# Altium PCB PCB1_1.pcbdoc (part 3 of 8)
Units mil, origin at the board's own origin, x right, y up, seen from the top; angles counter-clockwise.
Board outline 3937.01 x 3346.46 mil, 6 copper layers (Top Layer, Signal-1, SIG, POWER, Signal-4, Bottom Layer), stack 60.565 mil thick; 256 components, 201 nets, 1360 pads, 815 vias.
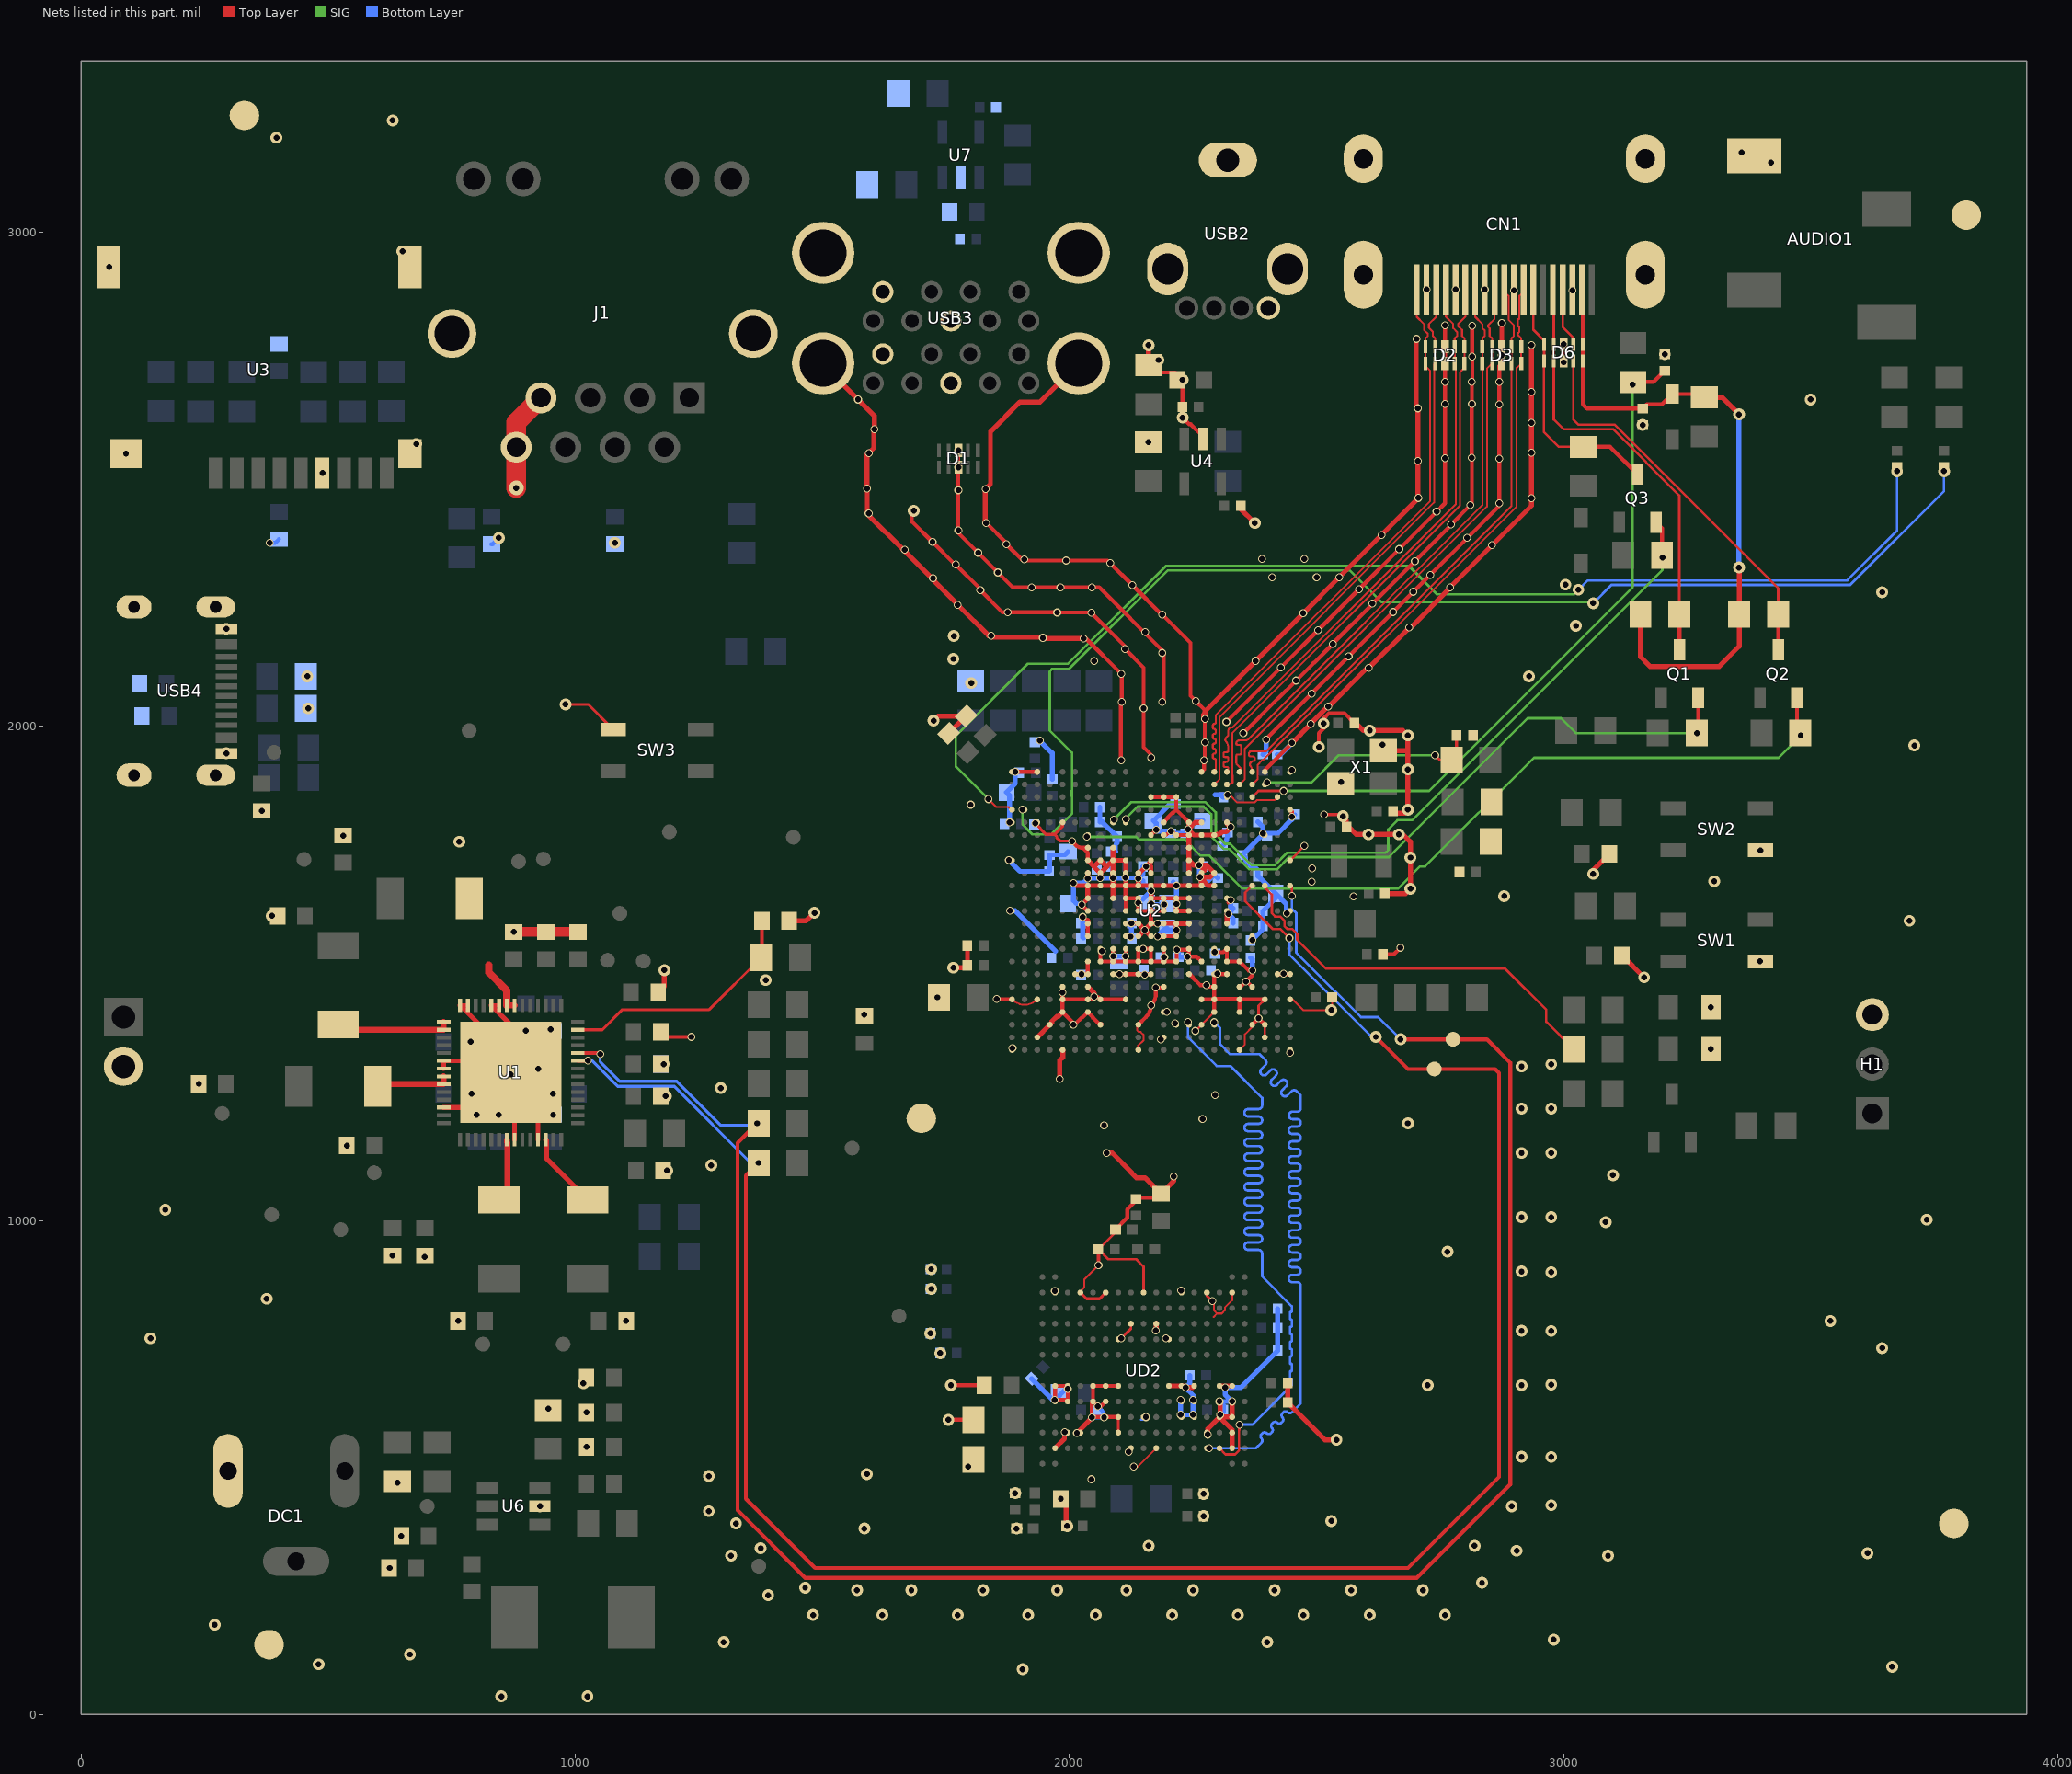
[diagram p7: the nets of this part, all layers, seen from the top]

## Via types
v1: diameter 16, hole 12, Top Layer to Bottom Layer, 426 vias
v2: diameter 24, hole 12, Top Layer to Bottom Layer, 385 vias
v3: diameter 34, hole 12, Top Layer to Bottom Layer, 2 vias
v4: diameter 30, hole 12, Top Layer to Bottom Layer, 2 vias

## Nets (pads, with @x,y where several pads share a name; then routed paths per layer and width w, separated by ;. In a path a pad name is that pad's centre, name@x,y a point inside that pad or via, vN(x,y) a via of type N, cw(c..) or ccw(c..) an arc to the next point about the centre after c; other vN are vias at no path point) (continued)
GND: AUDIO1.1 C1.1 C2.1 C3.1 C4.1 C5.1 C6.1 C7.1 C8.1 C9.1 C10.1 C11.1 C12.1 C13.1 C14.1 C15.1 C16.1 C17.1 C18.1 C19.1 C20.1 C21.1 C24.1 C25.2 C26.1 C27.1 C28.1 C29.1 C30.1 C31.1 C32.1 C33.1 C34.1 C35.1 C36.1 C37.1 C38.1 C39.1 C40.1 C41.1 C42.1 C43.1 C44.1 C45.1 C46.1 C47.1 C48.1 C49.1 C50.1 C51.1 C52.1 C53.1 C54.1 C55.1 C56.1 C57.1 C58.1 C59.1 C60.1 C61.1 C62.1 C63.1 C64.1 C65.1 C66.1 C67.1 C68.1 C69.1 C70.1 C71.1 C72.1 C73.1 C74.1 C75.1 C76.1 C77.1 C78.1 C79.1 C80.1 C81.1 C82.1 C83.1 C84.1 C85.1 C86.2 C87.2 C88.2 C89.2 C90.1 C91.1 C92.1 C93.1 C94.1 C95.1 C96.1 C97.1 C98.1 C99.1 C100.1 C101.1 C102.1 C103.1 C104.1 C105.1 C106.1 C107.1 C108.1 C109.1 C110.1 C111.1 C112.1 C113.1 C114.1 C115.1 C116.1 C117.1 C118.1 C119.1 C120.1 C121.1 C122.1 C123.2 C124.1 C125.2 C126.1 C127.1 C128.2 C129.1 C130.1 C131.1 C132.2 C135.1 C136.1 C137.1 C138.1 C139.2 C140.2 C141.1 C142.2 C143.2 C144.2 C147.1 C148.1 C149.2 CN1.2 CN1.5 CN1.8 CN1.11 CN1.17 CN1.20 CN1.21 CN1.22 CN1.23 D1.3 D1.8 D2.3 D2.8 D3.3 D3.8 D6.3 D6.8 DC1.2 H1.3 H2.2 J1.7 J1.8 J1.SH1 J1.SH2 LED1.1 LED2.1 pad.1@330,3236.46 pad.1@3815,3034.92 pad.2@3790,386.46 pad.3@380,141.46 pad.4@1700,1206.46 R7.2 R16.1 R17.1 R18.2 R21.1 R24.1 R30.2 R31.1 R34.1 R37.1 R38.1 R44.1 R55.1 R65.1 R67.2 R69.1 SW1.4 SW2.4 SW3.4 U1.8 U1.11 U1.37 U1.38 U1.41 U1.42 U1.48 U1.49 U1.54 U1.57 U2.A1 U2.A3 U2.A16 U2.A21 U2.A23 U2.AA4 U2.AA8 U2.AA11 U2.AA14 U2.AA16 U2.AA20 U2.AA21 U2.AB3 U2.AB13 U2.AB21 U2.AC1 U2.AC5 U2.AC11 U2.AC19 U2.AC23 U2.C12 U2.C13 U2.C14 U2.C18 U2.C22 U2.D23 U2.E1 U2.E3 U2.E5 U2.E13 U2.E15 U2.E16 U2.E18 U2.F12 U2.F13 U2.F14 U2.F15 U2.F16 U2.F17 U2.F21 U2.G7 U2.G9 U2.G15 U2.H1 U2.H7 U2.H8 U2.H9 U2.H10 U2.H12 U2.H15 U2.H16 U2.H23 U2.J7 U2.J8 U2.J9 U2.J10 U2.J11 U2.J12 U2.J15 U2.J16 U2.J17 U2.K7 U2.K8 U2.K9 U2.K10 U2.K11 U2.K12 U2.K13 U2.K14 U2.K15 U2.K16 U2.K17 U2.L7 U2.L9 U2.L10 U2.L11 U2.L12 U2.L13 U2.L14 U2.L15 U2.L18 U2.M1 U2.M7 U2.M10 U2.M11 U2.M12 U2.M13 U2.M14 U2.M15 U2.M18 U2.M23 U2.N7 U2.N10 U2.N11 U2.N12 U2.N13 U2.N14 U2.N15 U2.N18 U2.P7 U2.P10 U2.P11 U2.P12 U2.P13 U2.P14 U2.P20 U2.R8 U2.R9 U2.R10 U2.R11 U2.R12 U2.R13 U2.R14 U2.R15 U2.R17 U2.R18 U2.T7 U2.T8 U2.T9 U2.T10 U2.T11 U2.T12 U2.T13 U2.T14 U2.T15 U2.T16 U2.T18 U2.T19 U2.U6 U2.U7 U2.U9 U2.U10 U2.U11 U2.U12 U2.U15 U2.U17 U2.U18 U2.U22 U2.U23 U2.V5 U2.V7 U2.V13 U2.V17 U2.V19 U2.V20 U2.W1 U2.W3 U2.W5 U2.W7 U2.W8 U2.W10 U2.W16 U2.W17 U2.W19 U2.W21 U2.W23 U2.Y5 U2.Y7 U2.Y13 U2.Y17 U2.Y19 U3.6 U3.10 U3.11 U3.12 U3.13 U4.2 U6.2 U7.2 UD2.B2 UD2.B5 UD2.B6 UD2.B12 UD2.C3 UD2.C5 UD2.C6 UD2.D3 UD2.D12 UD2.E4 UD2.E5 UD2.E6 UD2.F4 UD2.F5 UD2.F6 UD2.F12 UD2.G3 UD2.G4 UD2.G6 UD2.G9 UD2.H2 UD2.H10 UD2.J4 UD2.J12 UD2.K2 UD2.K10 UD2.L6 UD2.L9 UD2.M4 UD2.M5 UD2.M6 UD2.M12 UD2.N4 UD2.N5 UD2.N6 UD2.P3 UD2.P12 UD2.R4 UD2.R5 UD2.R6 UD2.T2 UD2.T3 UD2.T4 UD2.T5 UD2.T6 UD2.T12 USB2.4 USB2.5 USB2.6 USB2.7 USB3.4 USB3.7 USB3.13 USB3.16 USB3.19 USB3.20 USB3.21 USB3.22 USB4.13 USB4.14 USB4.A1B12 USB4.B1A12 X1.1 X1.3 | length 21530.1
  Top Layer w4: U2.W1@1883.5,1447.32 cw(c1883.5,1445.8) 1884.58,1446.88 1885.49,1445.97 ccw(c1908.45,1468.93) 1908.45,1436.46 ccw(c1908.45,1473.56) U2.W3@1934.69,1447.32 ; UD2.D12@2019.4,853.78 2030,864.38 2030,880.37 v1(2058.73,909.09) ; v1(2120,531.46) 2124.41,535.87 UD2.H2@2124.41,538.98 ; v1(2130,501.46) 2138.07,501.46 UD2.K2@2175.59,538.98 ; U2.AC11@2139.41,1344.96 2139.41,1354.1 2149.84,1364.53 2149.84,1365.56 2150.31,1366.03 2150.31,1375.07 2143.93,1381.46 2140,1381.46 2137.17,1384.29 2137.17,1393.9 U2.AA11@2139.41,1396.14 ; v1(2185,1366.46) 2186.5,1366.46 U2.AB13@2190.59,1370.55 ; U2.AA16@2269.09,1397.87 U2.Y17@2292.95,1421.73 ; v1(2288.93,836.72) 2288.93,832.47 2292.64,828.76 2292.64,817.52 2298.62,811.54 ; 2291.77,804.68 2298.62,811.54 ; v1(2320,1861.46) 2324.03,1861.46 2339.62,1845.87 2374.24,1845.87 2378.96,1850.59 2414.72,1850.59 U2.C22@2420.91,1856.77 ; UD2.T12@2329.13,853.94 2329.13,838.46 2314.45,823.78 2314.45,817.92 2308.06,811.54 2298.62,811.54 ; U2.AC19@2344.13,1344.96 2355,1355.83 2355,1376.46 2369.72,1391.18 U2.AA20@2369.72,1396.14 ; U2.AB21@2395.31,1370.55 U2.AA21@2395.31,1396.14 ; U2.W23@2446.5,1447.32 2451.64,1447.32 2473.42,1425.54 v2(2530,1425.54) 2531.54,1427.08 C51.1@2531.54,1451.46
  Top Layer w5: C92.1@2058.46,941.46 2092.96,975.96 R21.1@2092.96,981.46 ; C92.1@2058.73,941.19 2078.46,921.46 2135,921.46 2150,906.46 UD2.J12@2150,853.94 ; UD2.G9@2098.82,759.45 2102.99,759.45 v1(2105,761.46) 2124.41,780.87 UD2.H10@2124.41,790.94 ; v1(2255.04,1383.54) 2267.36,1395.86 U2.AA16@2267.36,1396.14 ; UD2.P12@2277.95,853.94 2277.95,847.71 v1(2288.93,836.72) ; v1(2382.65,1408.8) 2382.65,1434.66 U2.W21@2395.31,1447.32 ; U2.H23@2446.5,1728.82 2475,1757.32 v1(2475,1758.46)
  Top Layer w6: v2(980,2044.46) 1025.74,2044.46 SW3.4@1076.42,1993.78 ; U2.E3@1929.71,1802.7 v1(1930.48,1803.47) 1952.49,1781.46 1970,1781.46 ; U2.E5@1985.87,1805.59 1985.87,1797.32 1970,1781.46 ; v1(2005,1767.09) 2004,1768.09 1980.93,1768.09 1973.96,1775.07 1973.96,1777.5 1970,1781.46 ; UD2.D12@2022.05,853.94 2034.53,841.46 2060.75,841.46 UD2.F12@2073.23,853.94 ; UD2.G3@2098.82,570.47 UD2.G4@2098.82,601.97 ; v1(2515,1821.46) v2@2549.97,1821.46
  Top Layer w8: U1.42@766.66,1435.16 U1.41@782.4,1435.16 ; U1.38@829.65,1435.16 U1.37@845.4,1435.16 ; C24.1@1018.02,670.36 1018.02,670.78 cw(c1033.12,670.78) C24.1@1022.44,681.46 ; C14.1@1172.56,1381.46 1182.56,1371.46 v1(1235,1371.46) ; v2(1685,2436.46) 1681.02,2432.48 1681.02,2414.48 1722.27,2373.24 v1(1722.8,2373.24) 1768.63,2327.41 v1(1769.81,2327.41) 1819.5,2277.71 v1(1819.5,2275.47) 1864.26,2230.71 v1(1874.67,2230.71) 1974.8,2230.71 v1(1975.05,2230.47) 2043.76,2230.47 v1(2044.5,2229.72) 2112.6,2161.63 v1(2112.6,2156.33) 2150,2118.93 v1(2150,2036.46) 2150,1957.87 2165,1942.87 v1(2165,1936.46) ; v2(1755,596.46) R30.2@1805.63,596.46 ; v2(1760,666.46) C122.1@1827.44,666.46 ; v1(1775,2558.5) v1(1775,2524.42) v1(1775,2478.07) v1(1775,2396.46) 1775,2391.46 v1(1815,2351.46) v1(1855,2311.46) 1885,2281.46 v1(1923.13,2281.46) v1(1981.58,2281.46) 2044.95,2281.46 2060.03,2281.43 2188,2153.46 v1(2188,2148.59) 2190.38,2146.21 2190.38,2051.47 v1(2188,2049.09) ; v1(1831.49,2411.7) 1872.3,2370.89 v1(1872.3,2368.86) 1903.13,2338.03 v1(1908.13,2338.03) 1910.48,2335.68 v1(1993.25,2335.68) 2077.13,2335.68 v1(2082.17,2330.64) v1(2127.09,2285.72) 2186.69,2226.12 v1(2188,2226.12) 2245,2169.12 2245,2061.96 v1(2255.55,2051.4) 2273.96,2033 2273.96,2029.91 ; v1(1852.78,1448.36) ccw(c1855.28,1450.86) 1855.28,1447.32 U2.W1@1883.5,1447.32 ; U2.A1@1883.5,1907.95 U2.A3@1934.69,1907.95 ; U2.V5@1985.87,1472.91 v1(1985.87,1461.19) U2.W5@1985.87,1447.32 ; 1990.47,664.96 UD2.B6@1970.87,664.96 1970.87,637.32 v1(1970,636.46) 1993.46,636.46 UD2.C5@1996.46,633.46 v1(1996.46,658.97) UD2.C6@1996.46,664.96 ; v1(2005,1767.09) 2011.71,1760.39 ccw(c2026.14,1774.83) 2026.14,1754.41 cw(c2025.5,1752.86) 2027.05,1753.5 ; U2.U6@2011.46,1498.5 U2.U7@2037.05,1498.5 U2.T7@2037.05,1524.09 ; v1(2026.4,1614.3) 2032.09,1608.61 2037.05,1608.61 ; v1(2028.49,2177.97) 2033.15,2177.97 v1(2105.11,2106.01) 2106,2105.12 v1(2106,2049.8) 2104.11,2047.9 2104.11,1932.35 v1(2105,1931.46) ; U2.P7@2037.05,1575.28 U2.N7@2037.05,1600.87 2037.05,1608.61 ; U2.M7@2037.05,1626.46 v1(2024.73,1638.81) U2.L7@2037.05,1651.13 ; U2.H7@2037.05,1728.82 2037.05,1744.41 2027.05,1754.41 U2.G7@2037.05,1754.41 ; U2.N7@2038.41,1599.51 2038.41,1607.25 2037.05,1608.61 ; v1(2045,601.46) 2045,630.83 UD2.E5@2047.64,633.46 ; UD2.E4@2045.51,601.97 UD2.F4@2070.51,601.97 ; v1(2057.5,623.56) 2063.33,623.56 UD2.F5@2073.23,633.46 ; v1(2057.5,623.56) UD2.E5@2047.64,633.46 ; C92.1@2058.46,941.46 2058.73,941.19 v1(2058.73,909.09) ; U2.R8@2062.64,1549.69 U2.T8@2062.64,1524.09 U2.T9@2088.23,1524.09 ; U2.AA8@2065.33,1397.33 2060.12,1397.33 2047.14,1410.31 2047.14,1411.64 U2.Y7@2037.05,1421.73 2026.96,1411.64 2025.63,1411.64 2010.32,1396.34 v1(2007.65,1396.34) 2007.65,1399.95 U2.Y5@1985.87,1421.73 U2.W5@1985.87,1447.32 ; v1(2070,601.46) UD2.F4@2070.51,601.97 ; UD2.F4@2073.23,601.97 UD2.G4@2098.82,601.97 ; UD2.F4@2073.23,604.68 UD2.F4@2070.51,601.97 ; U2.U9@2088.23,1498.5 U2.U10@2113.82,1498.5 U2.U11@2139.41,1498.5 U2.U12@2165,1498.5 ; U2.R9@2088.23,1549.69 U2.T9@2088.23,1524.09 ; R21.1@2092.96,981.46 2116.9,1005.4 2116.9,1022.19 2135,1040.29 C114.1@2135,1043 2138.02,1046.02 2177,1046.02 C93.1@2185,1054.02 ; UD2.G6@2098.82,664.96 UD2.F6@2073.23,664.96 UD2.E6@2047.64,664.96 UD2.E5@2047.64,633.46 ; U2.W10@2113.82,1447.32 U2.W8@2062.64,1447.32 2057.43,1452.53 v1(2050.23,1452.53) 2045.02,1447.32 U2.W7@2037.05,1447.32 U2.W5@1985.87,1447.32 ; U2.R10@2113.82,1549.69 U2.T10@2113.82,1524.09 ; U2.M10@2113.82,1626.46 U2.L10@2113.82,1652.05 U2.L11@2139.41,1652.05 U2.M11@2139.41,1626.46 U2.M12@2165,1626.46 U2.M13@2185,1626.46 ; U2.AA11@2139.41,1396.14 2155.47,1412.2 ccw(c2132.46,1435.21) v1(2165,1435.21) ccw(c2141.26,1458.95) 2174.83,1458.95 v1(2174.83,1471.18) 2188.85,1471.18 U2.V13@2190.59,1472.91 ; 2148.2,1524.89 2147.41,1524.09 U2.T12@2165,1524.09 ; R24.1@2160,2730.83 2174.37,2716.46 2214,2716.46 v2(2229,2701.46) 2228.46,2700.92 C126.1@2228.46,2646.46 2228.95,2645.97 v2(2228.95,2624.98) 2242.28,2611.65 2245.15,2611.65 2270,2586.8 U4.2@2270,2581.88 ; U2.L12@2165,1652.05 U2.L13@2190.59,1652.05 U2.L14@2216.18,1652.05 U2.L15@2241.77,1652.05 ; U2.F12@2165,1780 2165,1780.27 v1(2175.59,1790.86) ; U2.C12@2165,1856.77 U2.C13@2190.59,1856.77 U2.C14@2216.18,1856.77 2216.18,1831.18 ; U2.R13@2190.59,1549.69 U2.T13@2190.59,1524.09 ; U2.P13@2190.59,1575.28 U2.P14@2216.18,1575.28 ; U2.N13@2190.59,1600.87 U2.N14@2216.18,1600.87 ; U2.F13@2190.59,1780 2195.39,1780 2205,1789.61 2206.57,1789.61 U2.F14@2216.18,1780 U2.F15@2241.77,1780 ; U2.E13@2190.59,1805.59 2198.59,1813.59 2198.59,1815.43 2208.58,1825.42 2210.42,1825.42 2216.18,1831.18 ; U2.R14@2216.18,1547.86 v1(2217.18,1547.86) ; U2.E15@2241.77,1805.59 2216.18,1831.18 ; U2.U15@2244.43,1497.42 2248.9,1492.96 2248.9,1492.04 2264.61,1476.32 v1(2277.11,1476.32) 2280.52,1472.91 U2.V17@2292.95,1472.91 ; U2.W16@2267.36,1447.32 2292.36,1447.32 U2.W17@2292.95,1448.06 ; U2.T16@2267.36,1524.09 2257.62,1533.84 v1(2239.16,1533.84) 2241.77,1536.45 U2.R15@2241.77,1549.69 2239.95,1547.86 v1(2217.18,1547.86) ; U2.A16@2267.36,1907.95 2272.36,1912.95 v1(2272.36,1931.15) 2273.96,1932.75 v1(2273.96,1967.44) v1(2273.96,2014.91) ; U2.Y17@2292.95,1421.73 U2.W17@2292.95,1447.32 ; U2.U17@2292.95,1498.5 U2.V17@2292.95,1472.91 ; v1(2293.87,1542.76) 2311.62,1542.76 U2.R18@2318.54,1549.69 U2.T18@2318.54,1524.09 U2.T19@2344.13,1524.09 2362.04,1506.19 v1(2370,1506.19) 2370,1496.29 v1(2356.98,1483.26) ; v1(2299.39,1499.79) 2300.67,1498.5 U2.U18@2318.54,1498.5 ; v1(2317.5,2008.96) v1(2427.6,2119.06) v1(2503.16,2194.62) v1(2585.97,2277.43) v1(2667.38,2358.84) v1(2742.94,2434.4) 2760,2451.46 v1(2760,2542.97) v1(2760,2652.26) v1(2760,2697.43) D2.3@2760,2734.42 D2.8@2760,2768.5 v1(2760,2811.46) ; v1(2321.4,1620.52) U2.M18@2321.4,1626.46 ; v1@2321.4,1643.85 v1(2326.24,1648.7) ; U2.W19@2343.35,1448.06 U2.W17@2292.95,1448.06 ; U2.Y19@2344.13,1421.73 U2.W19@2344.13,1447.32 U2.W21@2395.31,1447.32 ; U2.V19@2344.13,1472.91 2346.63,1472.91 v1(2356.98,1483.26) ; v1(2351.87,1986.29) 2420.92,2055.33 2421.26,2055.33 v1(2458.7,2092.77) 2458.7,2092.94 2494.09,2128.34 2494.77,2128.34 v1(2533.1,2166.67) 2533.1,2167.52 2613.37,2247.79 v1(2613.37,2248.64) v1(2699.13,2334.39) 2772.26,2407.53 v1(2772.26,2408.72) 2772.64,2408.72 2811.04,2447.12 v1(2811.04,2447.5) 2814.5,2450.96 2814.5,2543.4 v1(2814.26,2543.64) 2814.26,2652.16 v1(2814.5,2652.41) 2814.5,2696.77 v1(2814.01,2697.26) 2815.31,2698.56 v1(2815.31,2748.39) 2815,2748.69 v1(2815,2810.83) ; U2.AA20@2369.72,1396.14 2382.39,1408.8 v1(2382.65,1408.8) U2.AA21@2395.31,1396.14 ; U2.V20@2369.72,1472.91 2359.38,1483.26 v1(2356.98,1483.26) ; U2.A21@2395.31,1907.95 2395.31,1911.37 v1(2450.2,1966.25) ; v1(2397.95,1973.5) 2397.95,1974.41 v1(2490,2066.46) v1(2565,2141.46) v1(2655,2231.46) v1(2695.94,2272.39) v1(2730,2306.46) v1(2805,2381.46) 2870,2446.46 v1(2870,2451.46) v1(2870,2541.46) v1(2870,2651.57) v1(2870,2697.3) 2870,2729.42 D3.3@2875,2734.42 ; U2.U22@2420.91,1498.5 U2.U23@2446.5,1498.5 ; U2.D23@2446.5,1831.18 2450,1827.68 v1(2450,1816.46) ; v2@2505,1951.46 2504.77,1951.68 v2(2504.77,1958.33) 2504.77,1986.23 2514.34,1995.8 v2(2514.34,2005.8) 2514.34,2015.8 2525,2026.46 2556.54,2026.46 C87.2@2576.54,2006.46 ; v2@2549.97,1821.46 v2(2553.36,1818.07) 2561.14,1810.28 C89.2@2561.14,1796.66 ; C84.1@2634.81,1538.47 2656.51,1538.47 v1(2670,1551.96) ; v1(2702.17,2784.28) 2702.17,2646.69 v1(2705.1,2643.76) ; U2.T9@2088.23,1524.09 U2.T10@2113.82,1524.09 ; U2.T10@2113.82,1524.09 U2.T11@2139.41,1524.09 U2.R11@2139.41,1549.69 U2.R12@2165,1549.69 U2.T12@2165,1524.09 ; U2.T12@2165,1524.09 U2.T13@2190.59,1524.09 ; U2.T13@2190.59,1524.09 U2.T14@2216.18,1524.09 2217.18,1525.09 v1(2217.18,1547.86) ; U2.W17@2292.95,1448.06 U2.V17@2292.95,1472.91
  Top Layer w10: U1.54@733.19,1228.47 801.47,1228.47 v4(868.93,1295.93) ; U1.49@733.19,1307.21 U1.48@733.19,1322.96 841.9,1322.96 v4(868.93,1295.93) ; U1.42@766.66,1435.16 U1.57@869.02,1332.8 ; U1.38@829.65,1435.16 869.02,1395.79 U1.57@869.02,1332.8 ; U1.8@876.89,1163.51 U1.57@876.89,1292.47 ; U1.11@924.14,1163.51 924.14,1245.22 U1.57@876.89,1292.47 ; C18.1@1167.56,1461.46 1180,1473.9 v2(1180,1506.46) ; C144.2@1432.56,1606.46 1466.67,1606.46 1468.17,1607.96 1469.08,1607.96 v2(1483.79,1622.67) ; USB3.20@1501.34,2734.72 1501.34,2732.12 v1(1572,2661.46) 1605,2628.46 v1(1605,2601.46) 1603.71,2600.17 1603.71,2563.2 v1(1593.71,2553.2) 1590,2549.48 v1(1590,2481.46) 1590.72,2480.73 1590.72,2434 v1(1593.51,2431.21) 1593.51,2427.2 1663.02,2357.69 v1(1666.24,2357.69) 1666.24,2354.97 1721.01,2300.19 v1(1723.74,2300.19) 1723.74,2296.73 1773.86,2246.6 v1(1773.86,2245.86) 1836.16,2183.56 v1(1841.36,2183.56) 1844.21,2180.71 1944.65,2180.71 v1(1946.14,2179.23) 1947.4,2177.97 v1(2028.49,2177.97) ; v2(1725,2011.46) 1734.49,2020.94 C63.1@1790.51,2020.94 C30.1@1755.51,1985.94 ; v2(1765,1511.46) 1788.46,1511.46 C91.1@1793.46,1516.46 C111.1@1793.46,1556.46 ; v1(1831.49,2411.7) 1829.54,2413.65 1829.54,2479.71 v1(1830,2480.17) 1840,2490.17 1840,2596.46 1900,2656.46 1940.39,2656.46 USB3.21@2018.66,2734.72 ; U2.AB3@1934.69,1370.55 U2.AA4@1960.28,1396.14 1964.37,1400.23 1964.37,1402.98 1974.03,1412.64 1976.78,1412.64 U2.Y5@1985.87,1421.73 ; UD2.B2@1970.87,538.98 1990,558.11 v1(1990,571.46) ; v1(1980,1286.46) 1980,1323.57 1986.38,1329.95 1986.38,1344.45 U2.AC5@1985.87,1344.96 ; v2(1982.44,436.46) 1993.46,425.44 C115.1@1993.46,381.46 ; v1(2008.34,1682.92) 2013.63,1677.64 U2.K7@2037.05,1677.64 ; v1(2015,569.6) UD2.E4@2045,599.6 ; U2.V7@2037.05,1472.91 2050.23,1459.73 v1(2050.23,1452.53) ; U2.L7@2037.05,1652.05 U2.K7@2037.05,1677.64 ; v1@2037.05,1692.29 U2.J7@2037.05,1703.23 ; U2.H7@2037.05,1728.82 2049.56,1716.31 ; 2049.56,1715.34 U2.J8@2061.66,1703.23 ; 2049.56,1715.74 U2.H8@2062.64,1728.82 2073.71,1717.75 ; v1@2062.64,1693.2 U2.J8@2062.64,1703.23 2073.71,1714.3 ; v1(2075,1136.46) 2086.33,1136.46 2125.5,1097.29 2125.5,1095.96 2135,1086.46 2152.56,1086.46 C93.1@2185,1054.02 2211.12,1080.14 v1(2211.12,1089.01) ; 2075.87,1716.46 U2.H9@2088.23,1728.82 ; U2.L9@2088.23,1652.05 U2.K9@2088.23,1677.64 ; U2.G9@2088.23,1754.41 U2.H9@2088.23,1728.82 ; U2.L10@2113.82,1652.05 U2.K10@2113.82,1677.64 ; v1(2125.3,1601.32) 2138.96,1601.32 U2.N11@2139.41,1600.87 2139.41,1600.66 v1(2152.23,1587.84) ; U2.P11@2139.41,1575.28 2139.67,1575.28 v1(2152.23,1587.84) ; v1(2155.16,1716.46) 2141.93,1703.23 U2.J11@2139.41,1703.23 v1(2139.42,1692.12) U2.K11@2139.41,1677.64 ; R24.1@2160,2730.83 v2(2160,2771.46) ; v1@2160.08,1721.38 2165,1726.3 U2.H12@2165,1728.82 ; U2.P12@2165,1575.28 2152.44,1587.84 v1(2152.23,1587.84) ; U2.J12@2165,1703.23 2165,1716.46 ; v1(2174.97,777.34) 2175.59,777.96 UD2.K10@2175.59,790.94 ; v1(2178.02,1575.12) 2190.43,1575.12 U2.P13@2190.59,1575.28 ; U2.N13@2190.23,1601.23 v1(2178.38,1601.23) 2178.02,1600.87 U2.N12@2165,1600.87 ; U2.M13@2190.59,1626.46 2191.05,1626.91 v1(2191.05,1639.44) 2191.05,1651.59 U2.L13@2190.59,1652.05 ; UD2.L6@2201.18,664.96 UD2.M6@2226.77,664.96 2231.5,664.96 v1(2235,661.46) 2248.86,661.46 UD2.N6@2252.36,664.96 ; U2.P14@2216.18,1575.28 v1(2216.18,1588.11) U2.N14@2216.18,1600.87 U2.N15@2241.77,1600.87 ; U2.L14@2216.64,1651.59 v1(2216.64,1640.43) 2216.64,1626.91 U2.M14@2216.18,1626.46 U2.M15@2241.77,1626.46 ; v1(2240,1791.46) 2251.46,1780 U2.F16@2267.36,1780 U2.F17@2292.95,1780 ccw(c2292.95,1803.39) 2309.49,1786.85 2317.32,1786.85 v1(2326.62,1796.15) 2325.92,1796.15 2320,1802.07 ccw(c2315.03,1802.07) U2.E18@2318.54,1805.59 ; U2.J15@2241.77,1703.23 U2.H15@2241.77,1728.82 ; U2.F15@2241.77,1780 U2.G15@2241.77,1754.41 U2.H15@2241.77,1728.82 ; U2.E15@2241.77,1805.59 2241.77,1793.23 2254.13,1805.59 U2.E16@2267.36,1805.59 ; U2.K16@2266.89,1679.83 v1@2266.89,1691.4 ; U2.K16@2267.36,1677.64 U2.K15@2241.77,1677.64 v1(2216.18,1677.64) U2.K13@2190.59,1677.64 U2.K12@2165,1677.64 ; 2272.97,1708.83 v1@2262.49,1719.3 ; 2273.96,2023 2273.96,2029.91 v1(2376.75,2132.71) v1(2472.94,2228.89) v1(2545.96,2301.92) v1(2631.61,2387.57) v1(2706.33,2462.29) 2705,2463.62 v1(2705,2537.29) 2705.1,2537.38 v1(2705.1,2643.76) ; v1(2280,566.46) 2280,578.43 UD2.R4@2303.54,601.97 2329.13,576.38 UD2.T3@2329.13,570.47 UD2.T2@2329.13,538.98 ; U2.K17@2292.95,1677.64 2280.65,1677.64 v1@2266.89,1691.4 ; v1(2303.54,633.46) 2305,632.01 v1(2305,606.46) 2309.49,601.97 UD2.T4@2329.13,601.97 v1(2329.13,633.46) ; UD2.R6@2303.54,664.96 2311.5,664.96 v1(2315,661.46) 2318.5,664.96 UD2.T6@2329.13,664.96 ; U2.N18@2319.1,1600.41 2319.1,1618.22 v1(2321.4,1620.52) ; C124.1@2346.54,2446.46 2346.54,2439.92 v2(2375,2411.46) ; C104.1@2441.54,671.46 C109.1@2441.54,631.46 2517,556 v2(2540.46,556) ; v1(2450.2,1966.25) 2488.06,2004.11 v1(2488.06,2004.44) 2488.06,2005.21 v1(2523.32,2040.47) 2524.82,2040.47 2602.78,2118.43 v1(2605.73,2118.43) 2606.36,2118.43 2687.61,2199.69 v1(2687.61,2199.92) 2690.47,2199.92 2770.2,2279.65 v1(2770.2,2281.25) 2855,2366.05 v1(2855,2366.46) 2935,2446.46 v1(2935,2461.46) v1(2935,2554.25) v1(2935,2614.05) v1(2935,2676.75) v1(2935,2771.46) ; C89.2@2561.14,1796.66 2564.79,1796.66 2580,1781.46 v2(2605.23,1781.46) 2675,1781.46 2690,1766.46 v2(2690,1734.46) v2(2690,1671.46) 2680.23,1661.69 C88.2@2638.46,1661.69 ; C87.2@2577.24,2009.22 2595,1991.46 v2(2607.85,1991.46) 2675,1991.46 v2(2685,1981.46) 2685,1950.82 ; X1.1@2635.31,1951 2684.82,1951 2685,1950.82 ; C86.2@2655.01,1828.46 2659.08,1824.39 2677.93,1824.39 v2(2685,1831.46) v2(2685,1912.85) 2685,1950.82 ; D3.8@2875,2768.5 v1(2875,2816.46) ; D6.3@3000,2739.42 v1(3000,2773.5) ; v2(3060,1701.46) 3060,1708.9 C143.2@3092.56,1741.46 ; C142.2@3117.56,1536.46 3118.47,1536.46 v2(3163,1491.93) ; v4(868.93,1295.93) 872.39,1292.47 U1.57@876.89,1292.47 ; v4(868.93,1295.93) 868.93,1332.71 U1.57@869.02,1332.8 ; U2.K7@2037.05,1677.64 U2.K8@2062.64,1677.64 U2.K9@2088.23,1677.64 ; U2.K9@2088.23,1677.64 U2.J9@2088.23,1703.23 U2.H9@2088.23,1728.82 ; U2.K9@2088.23,1677.64 U2.K10@2113.82,1677.64 ; U2.H9@2088.23,1728.82 U2.H10@2113.82,1728.82 U2.J10@2113.82,1703.23 U2.K10@2113.82,1677.64 ; U2.K10@2113.82,1677.64 U2.K11@2139.41,1677.64 ; U2.K11@2139.41,1677.64 U2.K12@2165,1677.64 ; v1(2152.23,1587.84) 2165,1600.61 U2.N12@2165,1600.87 ; U2.N12@2165,1600.87 U2.M12@2165,1626.46 v1(2165,1640.82) U2.L12@2165,1652.05 2165.17,1652.22 v1(2165.17,1666.71) 2165.17,1677.47 U2.K12@2165,1677.64 ; U2.H15@2241.77,1728.82 2251.29,1719.3 v1(2261.73,1719.3) v1@2262.49,1719.3 ; v1@2262.49,1719.3 2276.88,1719.3 U2.J17@2292.95,1703.23 2284.25,1694.52 v1(2263.76,1694.52) v1@2266.89,1691.4
  Top Layer w15: v1(2273.96,2014.91) 2273.96,2023 ; D3.3@2875,2734.42 v1(2875,2751.15) D3.8@2875,2768.5
  Top Layer w20: v2(875,1584.02) C17.1@940,1584.02 C25.2@1005,1584.02
  Top Layer w40: v4(880.2,2482.46) J1.8@880.2,2565 880.2,2615 J1.7@930.2,2665
  Bottom Layer w5: 2145,596.46 ccw(c2145,606.88) 2152.37,599.51 v1(2154.66,601.8)
  Bottom Layer w8: v1(381,2371.46) 392.56,2371.46 C130.1@400,2378.9 ; C138.1@830,2368.9 832.44,2368.9 v2(845,2381.46) ; 2014.25,1641.46 2022.09,1641.46 v1(2024.73,1638.81) ; v1@2040.5,596.96 v1(2045,601.46) v1(2070,601.46) ccw(c2046.8,601.46) 2063.2,617.86 v1(2057.5,623.56) ; v1(2088.58,1534.87) C117.1@2113.47,1534.87 ; 2094.07,1762.09 2094.07,1746.87 2094.49,1746.46 ; v1(2450,1816.46) 2451.54,1816.46 C65.1@2456.54,1821.46
  Bottom Layer w10: v1(1877.29,1729) 1899.83,1706.46 C67.1@1958.46,1706.46 1959.73,1707.73 C35.1@1959.73,1739.92 1990.95,1739.92 C54.1@1997.19,1746.15 ; v1(1878.61,1806) 1878.61,1860.28 C53.1@1872.44,1866.46 1890.35,1884.37 v1(1890.35,1907.67) ; v1(1879.26,1626.58) 1890.26,1626.58 1971.92,1544.92 ; C103.1@1923.3,679.76 1966.61,636.46 v1(1970,636.46) 1992.51,658.97 v1(1996.46,658.97) ; v1(1939.84,1971.14) 1965,1945.98 C34.1@1965,1893 ; 2014.25,1641.46 2008.34,1647.36 v1(2008.34,1682.92) 2027.91,1682.92 v1(2037.27,1692.29) 2038.19,1693.2 v1(2062.41,1693.2) ; C74.1@2028.46,1571.46 2026.65,1573.27 C73.1@2026.65,1603.27 ; C73.1@2028.46,1601.46 C73.1@2026.65,1603.27 ; C26.1@2055,1709.92 2062.41,1702.51 v1(2062.41,1693.2) ; C56.1@2061.54,1836.46 C55.1@2061.54,1806.46 2066.54,1806.46 C37.1@2096.54,1776.46 2096.54,1764.56 2094.07,1762.09 ; C90.1@2083.46,1716.46 2088.46,1711.46 v1(2088.46,1692.68) ; v1(2123.32,1574.34) 2125.3,1576.32 v1(2125.3,1601.32) ; v1(2139.18,1642.71) v1@2141.16,1642.71 ; C78.1@2148.46,1716.46 2148.46,1701.15 2140.88,1693.57 v1(2113.48,1693.57) 2112.58,1692.68 v1(2088.46,1692.68) ; C32.1@2148.61,1687.35 2148.61,1683.27 v1(2165.17,1666.71) C72.1@2148.74,1650.28 ; C72.1@2163.12,1642.71 v1(2165,1640.82) ; C72.1@2166.38,1639.44 v1(2191.05,1639.44) ; v1(2178.02,1575.12) 2191.01,1588.11 v1(2216.18,1588.11) ; v1(2178.38,1601.23) 2187.67,1601.23 C61.1@2197.44,1591.46 ; C46.1@2210,1684.92 2216.18,1678.74 v1(2216.18,1677.64) 2216.64,1677.18 v1(2216.64,1640.43) ; C33.1@2215,1843 2203.98,1843 C82.1@2170,1809.02 2175.59,1803.42 v1(2175.59,1790.86) 2178.38,1788.07 v1(2205,1788.07) 2210.08,1783 C45.1@2235,1783 2235,1786.46 v1(2240,1791.46) 2257.56,1809.02 C77.1@2270,1809.02 ; v1(2217.18,1547.86) 2220,1545.04 C121.1@2220,1533 2238.32,1533 v1(2239.16,1533.84) ; v1(2225,636.46) v1(2225,606.46) v1(2250,606.46) v1(2250,636.46) 2250,646.46 v1(2235,661.46) 2243.46,669.92 C95.1@2243.46,686.46 ; v1(2261.73,1719.3) 2263.3,1717.73 2263.3,1694.98 v1(2263.76,1694.52) ; C38.1@2271.54,1686.75 C38.1@2271.54,1686.46 2280.41,1686.46 2293.47,1699.52 C62.1@2300,1693 ; 2295,1861.46 C59.1@2306.18,1861.46 ; v1(2305,606.46) 2311.54,613 C101.1@2311.54,616.46 2311.54,625.47 v1(2303.54,633.46) v1(2329.13,633.46) 2315,647.6 v1(2315,661.46) 2346.54,661.46 C94.1@2421.54,736.46 C96.1@2421.54,781.46 C97.1@2421.54,821.46 ; C58.1@2310,1758 ccw(c2285.86,1782.14) 2320,1782.14 C81.1@2320,1784.92 ; C59.1@2311.27,1856.37 C59.1@2306.18,1861.46 ; v1(2320,1861.46) C59.1@2306.18,1861.46 ; v1(2326.24,1648.7) C68.1@2326.24,1625.36 ; C70.1@2331.54,1601.46 2331.54,1610.37 v1(2321.4,1620.52) C68.1@2326.24,1625.36 ; C68.1@2331.54,1631.46 2331.54,1630.66 C68.1@2326.24,1625.36 ; C108.1@2366.54,1531.46 2370,1527.99 v1(2370,1506.19) ; v1(2369.69,1567.59) 2391.54,1589.44 C44.1@2391.54,1596.46 C52.1@2391.54,1626.46 2417.56,1652.48 C48.1@2417.56,1661.46 ; C39.1@2381.54,1806.46 2391.26,1796.74 v1(2391.26,1783.64) ; C64.1@2391.34,1943 2397.95,1949.62 v1(2397.95,1973.5) ; C41.1@2420,1943 2426.95,1943 v1(2450.2,1966.25) ; v1(2440,1621.46) 2440,1624.99 2438.5,1626.49 2438.5,1640.52 C48.1@2417.56,1661.46 ; v1(2450,1816.46) 2450,1811.46 2422.19,1783.64 v1(2391.26,1783.64) ; C73.1@2026.65,1603.27 2026.65,1614.06 v1(2026.4,1614.3) 2026.4,1603.51 C73.1@2026.65,1603.27 ; v1(2062.41,1693.2) 2087.93,1693.2 v1(2088.46,1692.68) ; v1(2391.26,1783.64) 2391.26,1781.18 C49.1@2350,1739.92 2356.13,1733.79 2356.13,1728.12 2365.8,1718.46 2371.46,1718.46 2381.54,1708.38 C50.1@2381.54,1696.46 2382.56,1696.46 C48.1@2417.56,1661.46
  other v1: 2044.71,476.05 2195,761.46 1970.37,857 2225.72,858.33 2070,1192.46 2269.2,1205.66 2294.5,1254.06 2446.69,1339.56 1884.69,1348.34 2214.01,1398.73 2196.69,1421.85 2024.33,1498.31 2101.16,1498.2 2151.99,1497.77 2433.47,1499.07 2191.82,1533.15 2113.5,1534.84 2065.35,1545.07 2149.11,1549.97 2575,1655.92 2490,1685.46 2491,1712.46 1800,1841.46 2450,1911.46 2050,2132.46 2152.97,2190.56 2044.97,2281.43 2500,2301.46 2410,2301.92 2390,2338.92 2475,2338.92 3000,2736.77 2899.67,2882.2 3017.78,2882.2 2722.51,2884.18 2781.57,2884.18 2840.61,2884.17
  other v2: 850,36.46 1024.25,36.46 1905,91.46 3665,96.46 480,101.46 665,121.46 1300,146.46 2400,146.46 2980,151.46 270,181.46 1481.01,201.46 1621.03,201.46 1773.79,201.46 1916.17,201.46 2052.9,201.46 2208.01,201.46 2340.49,201.46 2473.45,201.46 2607.82,201.46 2760,201.46 1390,241.46 1570,251.46 1680,251.46 1825,251.46 1975,251.46 2115,251.46 2250,251.46 2415,251.46 2570,251.46 2715,251.46 1465,256.46 2835,266.46 624.41,296.46 1315,321.46 3090,321.46 3615,326.46 2905,331.46 1375,336.46 2160,341.46 2820,341.46 647.44,361.46 1585,376.46 1892.96,376.46 1995.24,381.46 1325,386.46 2530,391.46 2271.54,401.46 1270,411.46 928.15,421.46 2895,421.46 2975,423.55 2271.54,446.46 1890,448 640,469.23 1270,482.48 1590,486.46 1795,501.46 2915,521.46 2975,521.14 1022.44,541.46 1022.44,611.46 945,618.68 2725,666.46 2915,666.46 2975,667.77 1016.29,670.07 1738.46,731.46 3645,741.46 140,761.46 1718.46,771.46 2915,776.46 2975,776.2 762.44,796.46 1102.56,796.46 3540,796.46 375,841.46 1720.24,861.46 2975,895.01 2915,896.46 1720,901.46 695,926.46 630,928.9 2765,936.46 3085,996.46 3735,1001.46 2915,1006.46 2975,1006.28 170,1021.46 3100,1091.46 1185.5,1100.95 1275,1111.46 2915,1136.46 2975,1136.46 537.44,1151.46 2685,1196.46 800,1214.02 845,1214.02 955,1214.02 2915,1226.46 2975,1226.46 1182.75,1251.45 790,1256.46 954.41,1256.46 1294.24,1267.88 237.44,1276.46 925,1306.46 2915,1311.46 1178.57,1316.46 2975,1316.04 3298.31,1346.46 787.56,1361.46 900,1383.9 950,1386.46 1585,1416.46 3298.31,1431.46 1732.78,1451.46 1385,1486.46 3397.6,1524.13 3700,1606.46 385.59,1616.46 2880,1656.46 3305,1686.46 3398.58,1749.13 765,1766.46 530,1779.02 2666.52,1781.46 365,1828.9 2550,1887.57 293.51,1945.47 3710,1961.46 2633.34,1962.81 459.04,2036.46 1801.16,2087.62 457.32,2101.46 2930,2101.46 1765,2136.46 1765.69,2182.69 293.51,2197.44 3025,2203.46 3645,2271.46 3004,2286.86 1080,2371.46 487.95,2512.8 90.31,2552.17 677.69,2571.61 2159.37,2575.2 3160,2609.92 3500,2661.46 2180,2741.46 3205,2753 56.12,2929.79 650,2961.46 395,3191.46 630,3226.46
  other v3: 3420,3141.46 3360,3161.46
HCEC: Q3.2 R53.1 U2.E9 | length 1571.6
  Top Layer w8: Q3.2@3187.4,2412.83 3199.37,2400.86 R53.1@3199.37,2346.46
  SIG w5: v1(2090,1811.46) 2125.34,1846.8 2275.11,1846.8 2296.11,1825.8 2296.11,1781.46 2315.23,1762.34 2325.08,1762.34 2367.96,1719.46 2415.83,1719.46 2440.83,1744.46 2640,1744.46 2645,1749.46 2645,1791.46 2663.54,1809.99 2693.54,1809.99 3200,2316.46 v2(3200,2341.46)
HDMI-5V: C139.1 CN1.18 D5.2 D6.5 D6.6 R19.2 R33.2 R36.2 | length 1362.1
  Top Layer w8: CN1.18@3037.47,2884.17 3039.37,2882.27 D6.6@3039.37,2773.5 D6.5@3039.37,2739.42 3039.37,2651.46 3047.83,2643 C139.1@3160,2643 3168.46,2651.46 3198.84,2651.46 D5.2@3220,2672.62 3278.21,2672.62 R19.2@3285,2665.83
  Top Layer w10: R33.2@3155.63,2226.46 3155.63,2140.83 3175,2121.46 3315,2121.46 3355.63,2162.09 R36.2@3355.63,2226.46 3355.63,2320.83 v2(3355,2321.46) ; R19.2@3285,2665.83 3320.63,2665.83 v2(3355,2631.46)
  Bottom Layer w10: v2(3355,2321.46) v2(3355,2631.46)
HDMI-CEC: CN1.13 D6.1 D6.10 Q3.3 R54.1 | length 522.7
  Top Layer w5: CN1.13@2939.05,2884.17 2939.05,2802.41 2960.63,2780.83 D6.10@2960.63,2773.5 D6.1@2960.63,2739.42 2960,2738.79 2960,2596.46 2990.63,2565.83 R54.1@3040,2565.83
  Top Layer w8: R54.1@3040,2565.83 3094.26,2565.83 Q3.3@3150,2510.08
HDMI-SCL: CN1.15 D6.2 D6.9 Q1.3 R33.1 | length 893.9
  Top Layer w5: CN1.15@2978.41,2884.17 2980.32,2882.27 D6.9@2980.32,2773.5 D6.2@2980.32,2739.42 2980.32,2621.14 3000,2601.46 3100,2601.46 3234.37,2467.09 R33.1@3234.37,2226.46
  Top Layer w8: R33.1@3234.37,2226.46 3235,2225.83 Q1.3@3235,2155.08
HDMI-SDA: CN1.16 D6.4 D6.7 Q2.3 R36.1 | length 952.8
  Top Layer w5: CN1.16@2998.1,2884.17 2998.1,2808.36 3019.69,2786.77 D6.7@3019.69,2773.5 D6.4@3019.69,2739.42 3019.69,2621.46 3030.69,2610.46 3103.73,2610.46 3434.37,2279.81 R36.1@3434.37,2226.46
  Top Layer w8: R36.1@3434.37,2226.46 3435,2225.83 Q2.3@3435,2155.08
HHPD: C140.1 R47.1 U2.C20 | length 1430.6
  Top Layer w5: U2.C20@2369.72,1856.77 2382.25,1869.3 v1(2433.7,1869.3)
  Top Layer w8: R47.1@3140,2697.09 3182.17,2697.09 C140.1@3205,2719.92
  SIG w5: v1(2433.7,1869.3) 2727.84,1869.3 3140,2281.46 v2(3140,2691.46)
HSCL: Q1.2 R49.2 U2.E10 | length 1457.6
  Top Layer w8: R49.2@3269.37,1986.46 3272.4,1989.49 Q1.2@3272.4,2057.83
  SIG w5: v1@2113.5,1813.21 2138.1,1837.8 2271.39,1837.8 2287.11,1822.07 2287.11,1777.07 2312.26,1751.92 2322.77,1751.92 2364.23,1710.46 2419.56,1710.46 2444.56,1735.46 2646.27,1735.46 2927.27,2016.46 2995,2016.46 3025,1986.46 v2(3270,1986.46)
  other v1: 2114.06,1811.81
HSDA: Q2.2 R52.2 U2.F7 | length 1691.2
  Top Layer w8: Q2.2@3472.4,2057.83 3472.4,1993.43 R52.2@3479.37,1986.46
  SIG w5: v1(2035,1776.46) 2135,1776.46 2140,1771.46 2232.64,1771.46 2265.61,1738.49 2282.97,1738.49 2350,1671.46 2664.54,1671.46 2709.54,1716.46 2720,1716.46 2940,1936.46 3435,1936.46 v2(3480,1981.46)
HTX0N: CN1.9 D3.2 D3.9 U2.B19 | length 1222
  Top Layer w4: U2.B19@2344.13,1882.36 2355,1893.23 2355,1955.14 2845,2445.14 2845,2724.1 D3.2@2855.32,2734.42 D3.9@2855.32,2768.5 2855.32,2785.59 2850.48,2790.43 2850.48,2805.45 2847.62,2808.31 2847.62,2812.31 2860.31,2824.99 CN1.9@2860.31,2884.17
HTX0P: CN1.7 D3.1 D3.10 U2.A19 | length 1222.2
  Top Layer w4: U2.A19@2344.13,1907.95 ccw(c2337.21,1914.87) 2347,1914.87 2339.59,1922.28 cw(c2344.77,1927.46) 2337.45,1927.46 2337.45,1939.46 cw(c2342.28,1939.46) 2338.86,1942.87 2343.59,1942.87 ccw(c2343.59,1947.7) 2347,1944.29 2347,1955.14 cw(c2355,1955.14) 2347.26,1957.18 2347.26,1959.18 ccw(c2342.43,1959.18) 2345.85,1962.59 2340.86,1962.59 cw(c2340.86,1967.42) 2337.45,1964 2337.45,1965.56 cw(c2343.34,1965.56) 2339.18,1969.73 cw(c2343.34,1965.56) 2343.34,1971.46 2355,1971.46 ccw(c2355,1982.31) 2362.68,1974.64 2835.63,2447.59 D3.1@2835.63,2734.42 D3.10@2835.63,2768.5 2835.63,2785.59 2840.48,2790.43 2840.48,2801.31 2835.62,2806.16 2835.62,2814.31 2820.94,2828.99 CN1.7@2820.94,2884.17
HTX1N: CN1.6 D2.5 D2.6 U2.B18 | length 1216.5
  Top Layer w4: U2.B18@2318.54,1882.36 2320.11,1882.36 ccw(c2320.11,1896.34) 2330,1886.46 2330,1900.13 ccw(c2328.12,1900.13) 2329.45,1901.46 2329.45,1985.91 2790,2446.46 2790,2716.46 2799.37,2725.83 D2.5@2799.37,2734.42 D2.6@2799.37,2768.5 2799.37,2785.59 2794.53,2790.43 2794.53,2802.34 2786.56,2810.31 2786.56,2814.31 2801.24,2828.99 CN1.6@2801.24,2884.17
HTX1P: CN1.4 D2.4 D2.7 U2.A18 | length 1215.9
  Top Layer w4: U2.A18@2318.54,1907.95 ccw(c2311.53,1914.97) 2321.45,1914.97 ccw(c2317.85,1914.97) 2320.4,1917.51 2316.14,1917.51 cw(c2316.14,1923.57) 2311.86,1919.29 2311.86,1925.63 cw(c2313.86,1925.63) 2312.44,1927.04 cw(c2313.86,1925.63) 2313.86,1927.63 2315.86,1927.63 ccw(c2315.86,1934.04) 2320.39,1929.51 2320.82,1929.93 ccw(c2319.29,1931.46) 2321.45,1931.46 2321.45,1934.46 ccw(c2316.62,1934.46) 2320.03,1937.87 2315.27,1937.87 cw(c2315.27,1942.7) 2311.86,1939.29 2311.86,1944.46 cw(c2316.69,1944.46) 2313.27,1947.87 2318.03,1947.87 ccw(c2318.03,1952.7) 2321.45,1949.29 2321.45,1955.89 ccw(c2299.43,1955.89) 2315,1971.46 cw(c2324.66,1971.46) 2317.83,1978.29 2320.68,1981.14 cw(c2321.45,1980.37) 2321.45,1981.46 2321.45,1990.27 cw(c2330.58,1990.27) 2324.12,1996.73 2325.43,1998.03 2330.26,1998.03 2782,2449.77 2782,2732.11 D2.4@2779.69,2734.42 D2.7@2779.69,2768.5 2779.69,2785.59 2784.53,2790.43 2784.53,2798.19 2776.56,2806.16 2776.56,2814.31 2761.88,2828.99 CN1.4@2761.88,2884.17
HTX2N: CN1.3 D2.2 D2.9 U2.B17 | length 1198.5
  Top Layer w4: U2.B17@2292.95,1882.36 2303.86,1893.27 2303.86,2019 2738,2453.14 2738,2732.1 D2.2@2740.32,2734.42 D2.9@2740.32,2768.5 2740.32,2785.59 2735.48,2790.43 2735.48,2798.57 2727.51,2806.54 2727.51,2814.31 2742.19,2828.99 CN1.3@2742.19,2884.17
HTX2P: CN1.1 D2.1 D2.10 U2.A17 | length 1199.3
  Top Layer w4: U2.A17@2292.95,1907.95 2295.86,1910.86 2295.86,1931.86 ccw(c2292.93,1931.86) 2292.93,1934.79 cw(c2292.93,1937.72) 2290,1937.72 2290,1941.86 cw(c2292.93,1941.86) 2292.93,1944.79 ccw(c2292.93,1947.72) 2295.86,1947.72 2295.86,1951.86 ccw(c2292.93,1951.86) 2292.93,1954.79 cw(c2292.93,1957.72) 2290,1957.72 2290,1961.86 cw(c2292.93,1961.86) 2292.93,1964.79 ccw(c2292.93,1967.72) 2295.86,1967.72 2295.86,1971.86 ccw(c2292.93,1971.86) 2292.93,1974.79 cw(c2292.93,1977.72) 2290,1977.72 2290,1981.86 cw(c2292.93,1981.86) 2292.93,1984.79 ccw(c2292.93,1987.72) 2295.86,1987.72 2295.86,1991.86 ccw(c2292.93,1991.86) 2292.93,1994.79 cw(c2292.93,1997.72) 2290,1997.72 2290,2001.86 cw(c2292.93,2001.86) 2292.93,2004.79 ccw(c2292.93,2007.72) 2295.86,2007.72 2295.86,2022.31 2730,2456.46 2730,2719.39 2720.63,2728.76 D2.1@2720.63,2734.42 D2.10@2720.63,2768.5 2720.63,2785.59 2725.48,2790.43 2725.48,2794.43 2717.51,2802.4 2717.51,2814.31 2702.82,2828.99 CN1.1@2702.82,2884.17
HTXCN: CN1.12 D3.5 D3.6 U2.B20 | length 1239.4
  Top Layer w4: U2.B20@2369.72,1882.36 2380.66,1893.29 2380.66,1922.11 2389.79,1931.24 2391.1,1931.24 2905,2445.14 2905,2725.05 D3.5@2914.37,2734.42 D3.6@2914.37,2768.5 2914.37,2785.59 2907.53,2792.43 2907.53,2795.44 2910.58,2798.49 2910.58,2807.56 ccw(c2909.06,2807.56) 2909.06,2809.08 cw(c2909.06,2810.61) 2907.53,2810.61 2907.53,2822.56 cw(c2909.06,2822.56) 2909.06,2824.08 ccw(c2909.06,2825.61) 2910.58,2825.61 2910.58,2871.26 2919.35,2880.03 CN1.12@2919.35,2884.17
HTXCP: CN1.10 D3.4 D3.7 U2.A20 | length 1240.5
  Top Layer w4: U2.A20@2369.72,1907.95 2369.72,1910.05 ccw(c2353.59,1910.05) 2365,1921.46 2365,1922.25 cw(c2372.75,1922.25) 2367.27,1927.73 cw(c2372.75,1922.25) 2372.75,1930 2373.85,1930 cw(c2380.66,1925.8) 2375,1931.46 2375,1934.46 ccw(c2370.17,1934.46) 2373.59,1937.87 ccw(c2370.17,1934.46) 2370.17,1939.29 2366.49,1939.29 cw(c2366.49,1942.87) 2363.95,1940.34 cw(c2366.24,1942.63) 2363,1942.63 2363,1944.46 cw(c2367.83,1944.46) 2364.41,1947.87 2365.13,1948.59 cw(c2368.55,1945.17) 2368.55,1950 2398.55,1950 2894.69,2446.15 D3.4@2894.69,2734.42 D3.7@2894.69,2768.5 2894.69,2785.59 2899.53,2790.43 2899.53,2811.93 2888.77,2822.69 2888.77,2871.25 2879.98,2880.03 CN1.10@2879.98,2884.17
KEYADC: C57.2 R14.1 U2.B21 | length 454
  Top Layer w6: v1(2740,1941.46) 2749.67,1931.79 R14.1@2773.39,1931.79 2783.46,1941.85 C57.2@2783.46,1981.46
  SIG w5: v1(2400,1886.46) 2490,1886.46 2545,1941.46 v1(2740,1941.46)
LINEOUTL: C145.2 U2.D2 | length 2518.8
  SIG w5: v1(1905,1831.37) 1905,1801.59 1925.13,1781.46 1963.23,1781.46 2005,1823.23 2005,1858.16 2004.69,1858.47 2004.69,1870.07 2005,1870.38 2005,1946.46 1960,1991.46 1960,2111.46 1965,2116.46 1999.51,2116.46 2198.97,2315.92 2567.28,2315.92 2631.22,2251.98 3057.48,2251.98 v2(3060,2249.46)
  Bottom Layer w5: v2(3060,2249.46) 3097,2286.46 3580,2286.46 3770,2476.46 v2(3770,2516.46)
LINEOUTR: C146.2 U2.D1 | length 2464.3
  Top Layer w4: v1(1836.13,1852.7) 1851.96,1836.87 1876.36,1836.87 U2.D1@1882.16,1831.06
  Top Layer w5: v2(3675,2516.46) C146.2@3675,2524.92
  SIG w5: v1(1836.13,1852.7) 1770,1918.82 1770,1981.46 1915,2126.46 1996.78,2126.46 2195.24,2324.92 2686.54,2324.92 2744.2,2267.25 3020.8,2267.25 v2(3030,2276.46)
  Bottom Layer w5: v2(3030,2276.46) 3049,2295.46 3574,2295.46 3675,2396.46 v2(3675,2516.46)
LXA: L10.2 U1.43 U1.44 | length 239.6
  Top Layer w12: L10.2@520,1396.62 520,1385.95 U1.44@733.19,1385.95 U1.43@733.19,1401.7
LXB: L9.2 U1.35 U1.36 | length 112
  Top Layer w12: U1.36@861.14,1435.16 U1.35@876.89,1435.16
  Top Layer w15: 825,1516.46 825,1501.46 861.14,1465.31 U1.36@861.14,1435.16
LXC: L1.2 U1.50 U1.51 | length 153.4
  Top Layer w12: L1.2@599.84,1271.46 599.84,1275.72 U1.51@733.19,1275.72 U1.50@733.19,1291.47
LXD: L8.2 U1.7 | length 133
  Top Layer w12: L8.2@845,1041.3 850,1041.3 862.5,1053.8 862.5,1157.15 861.14,1158.51 U1.7@861.14,1163.51
LXE: L7.2 U1.12 | length 157.5
  Top Layer w10: U1.12@939.88,1163.51 941.63,1161.76 941.63,1124.96 1025,1041.59 L7.2@1025,1041.3
PMU-SCK: pad.1@2738.27,1306.46 R2.2 U1.23 U2.K20 | length 4509.9
  Top Layer w5: U2.K20@2369.72,1677.64 2355.54,1663.45 2355.54,1645.92 2412,1589.46 2427,1589.46 v1(2445,1571.46)
  Top Layer w8: U1.23@1004.84,1322.96 1024.95,1322.96 v1(1025.28,1323.29) ; v2(1370.63,1116.46) 1345,1090.83 1345,436.46 1485,296.46 2685,296.46 2869.39,480.85 2869.39,1298.46 2861.39,1306.46 ; v2(2620,1371.46) 2685,1306.46 ; 2685,1306.46 2861.39,1306.46 ; 2685,1306.46 pad.1@2738.27,1306.46 2861.39,1306.46
  Bottom Layer w5: v1(2445,1571.46) 2445,1538.12 2611.66,1371.46 v2(2620,1371.46)
  Bottom Layer w6: v1(1025.28,1323.29) 1033.59,1323.29 1085.42,1271.46 1200,1271.46 1355,1116.46 v2(1370.63,1116.46)
PMU-SDA: pad.2@2776.36,1366.46 R3.2 U1.24 U2.K23 | length 4627.9
  Top Layer w5: U2.K23@2446.5,1677.64 2450,1674.13 v1(2450,1656.46)
  Top Layer w8: U1.24@1004.84,1338.71 1018.58,1338.71 1018.72,1338.85 1047.61,1338.85 v1(1050,1336.46) ; v2(1367.68,1196.46) 1328,1156.78 1328,413.46 1465,276.46 2702.97,276.46 2892,465.49 2892,1319.46 2845,1366.46 ; 2845,1366.46 v2(2670,1366.46) pad.2@2776.36,1366.46 2845,1366.46
  Bottom Layer w5: v1(2450,1656.46) 2450,1631.26 2459,1622.26 2459,1542 2537.54,1463.46 2538,1463.46 2590,1411.46 2625,1411.46 v2(2670,1366.46)
  Bottom Layer w6: v1(1050,1336.46) 1050,1321.02 1089.56,1281.46 1205,1281.46 1294.24,1192.21 1363.43,1192.21 v2(1367.68,1196.46)
POWER: C144.1 R60.1 U1.27 | length 506.8
  Top Layer w6: U1.27@1004.84,1385.95 1054.49,1385.95 1095,1426.46 1270.63,1426.46 R60.1@1375.63,1531.46
  Top Layer w8: R60.1@1375.63,1531.46 1377.44,1533.27 C144.1@1377.44,1606.46
PWR-LED: R50.1 U2.K21 | length 814.3
  Top Layer w5: U2.K21@2395.31,1677.64 2395.31,1673.41 2409.5,1659.23 2409.5,1621.73 2416.18,1615.05 2426.61,1615.05 2435.09,1606.57 2435.09,1596.14 2441.77,1589.46 2451.22,1589.46 2461,1579.68 2461,1567.73 2519.27,1509.46 2882,1509.46 2965,1426.46 2965,1402.09 R50.1@3020.63,1346.46
SA0: U2.AA15 UD2.R2 | length 1691.3
  Top Layer w5: UD2.R2@2303.54,538.98 2316.06,526.46 2335,526.46 2343.32,534.78 2343.32,575.2 2343.74,575.61 v1(2343.74,586.22)
  Bottom Layer w5: v1(2239.92,1401.98) 2239.92,1370.17 2297.63,1312.46 2325.46,1312.46 2390,1247.91 2390,1232.91 cw(c2382.5,1232.91) 2382.5,1225.41 2361.5,1225.41 ccw(c2361.5,1217.91) 2361.5,1210.41 2382.5,1210.41 cw(c2382.5,1202.91) 2382.5,1195.41 2361.5,1195.41 ccw(c2361.5,1187.91) 2361.5,1180.41 2382.5,1180.41 cw(c2382.5,1172.91) 2382.5,1165.41 2361.5,1165.41 ccw(c2361.5,1157.91) 2361.5,1150.41 2382.5,1150.41 cw(c2382.5,1142.91) 2382.5,1135.41 2361.5,1135.41 ccw(c2361.5,1127.91) 2361.5,1120.41 2382.5,1120.41 cw(c2382.5,1112.91) 2382.5,1105.41 2361.5,1105.41 ccw(c2361.5,1097.91) 2361.5,1090.41 2382.5,1090.41 cw(c2382.5,1082.91) 2382.5,1075.41 2361.5,1075.41 ccw(c2361.5,1067.91) 2361.5,1060.41 2382.5,1060.41 cw(c2382.5,1052.91) 2382.5,1045.41 2361.5,1045.41 ccw(c2361.5,1037.91) 2361.5,1030.41 2382.5,1030.41 cw(c2382.5,1022.91) 2382.5,1015.41 2361.5,1015.41 ccw(c2361.5,1007.91) 2361.5,1000.41 2382.5,1000.41 cw(c2382.5,992.91) 2382.5,985.41 2361.5,985.41 ccw(c2361.5,977.91) 2361.5,970.41 2382.5,970.41 cw(c2382.5,962.91) 2382.5,955.41 2361.5,955.41 ccw(c2361.5,947.91) 2361.5,940.41 2382.5,940.41 cw(c2382.5,932.91) 2390,932.91 2390,886.46 2450,826.46 2450,816.64 cw(c2448.1,816.64) 2448.1,814.74 ccw(c2448.1,812.84) 2446.2,812.84 2446.2,801.64 ccw(c2448.1,801.64) 2448.1,799.74 cw(c2448.1,797.84) 2450,797.84 2450,786.64 cw(c2448.1,786.64) 2448.1,784.74 ccw(c2448.1,782.84) 2446.2,782.84 2446.2,771.64 ccw(c2448.1,771.64) 2448.1,769.74 cw(c2448.1,767.84) 2450,767.84 2450,756.64 cw(c2448.1,756.64) 2448.1,754.74 ccw(c2448.1,752.84) 2446.2,752.84 2446.2,741.64 ccw(c2448.1,741.64) 2448.1,739.74 cw(c2448.1,737.84) 2450,737.84 2450,726.64 cw(c2448.1,726.64) 2448.1,724.74 ccw(c2448.1,722.84) 2446.2,722.84 2446.2,711.64 ccw(c2448.1,711.64) 2448.1,709.74 cw(c2448.1,707.84) 2450,707.84 2450,696.64 cw(c2448.1,696.64) 2448.1,694.74 ccw(c2448.1,692.84) 2446.2,692.84 2446.2,681.64 ccw(c2448.1,681.64) 2448.1,679.74 cw(c2448.1,677.84) 2450,677.84 2450,666.46 2370.44,586.89 2344.41,586.89 v1(2343.74,586.22)
SA1: U2.AA17 UD2.P2 | length 1694.4
  Bottom Layer w5: v1(2282.95,538.98) 2377.52,538.98 2388.57,550.03 ccw(c2384.25,554.35) 2388.57,558.66 cw(c2392.89,562.98) 2388.57,567.3 2390.54,569.27 cw(c2394.86,564.95) 2399.18,569.27 ccw(c2403.5,573.59) 2407.81,569.27 2409.78,571.24 ccw(c2405.47,575.56) 2409.78,579.88 cw(c2414.1,584.2) 2409.78,588.51 2411.76,590.48 cw(c2416.07,586.17) 2420.39,590.48 ccw(c2424.71,594.8) 2429.03,590.48 2431,592.45 ccw(c2426.68,596.77) 2431,601.09 cw(c2435.32,605.41) 2431,609.73 2432.97,611.7 cw(c2437.29,607.38) 2441.6,611.7 ccw(c2445.92,616.02) 2450.24,611.7 2468,629.46 2468,867.51 ccw(c2460.5,867.51) 2460.5,875.01 2451.06,875.01 cw(c2451.06,882.51) 2451.06,890.01 2460.5,890.01 ccw(c2460.5,897.51) 2460.5,905.01 2451.06,905.01 cw(c2451.06,912.51) 2451.06,920.01 2460.5,920.01 ccw(c2460.5,927.51) 2460.5,935.01 2451.06,935.01 cw(c2451.06,942.51) 2451.06,950.01 2460.5,950.01 ccw(c2460.5,957.51) 2460.5,965.01 2451.06,965.01 cw(c2451.06,972.51) 2451.06,980.01 2460.5,980.01 ccw(c2460.5,987.51) 2460.5,995.01 2451.06,995.01 cw(c2451.06,1002.51) 2451.06,1010.01 2460.5,1010.01 ccw(c2460.5,1017.51) 2460.5,1025.01 2451.06,1025.01 cw(c2451.06,1032.51) 2451.06,1040.01 2460.5,1040.01 ccw(c2460.5,1047.51) 2460.5,1055.01 2451.06,1055.01 cw(c2451.06,1062.51) 2451.06,1070.01 2460.5,1070.01 ccw(c2460.5,1077.51) 2460.5,1085.01 2451.06,1085.01 cw(c2451.06,1092.51) 2451.06,1100.01 2460.5,1100.01 ccw(c2460.5,1107.51) 2460.5,1115.01 2451.06,1115.01 cw(c2451.06,1122.51) 2451.06,1130.01 2460.5,1130.01 ccw(c2460.5,1137.51) 2460.5,1145.01 2451.06,1145.01 cw(c2451.06,1152.51) 2451.06,1160.01 2460.5,1160.01 ccw(c2460.5,1167.51) 2460.5,1175.01 2451.06,1175.01 cw(c2451.06,1182.51) 2451.06,1190.01 2460.5,1190.01 ccw(c2460.5,1197.51) 2460.5,1205.01 2451.5,1205.01 cw(c2451.5,1212.51) 2451.5,1220.01 2460.5,1220.01 ccw(c2460.5,1227.51) 2468,1227.51 2468,1253.46 2460.07,1261.39 ccw(c2454.77,1256.08) 2449.46,1261.39 2441.43,1253.36 cw(c2436.13,1258.66) 2430.83,1263.96 2438.86,1271.99 ccw(c2433.55,1277.3) 2428.25,1282.6 2420.22,1274.57 cw(c2414.92,1279.87) 2409.61,1285.18 2417.64,1293.21 ccw(c2412.34,1298.51) 2407.04,1303.81 2399.01,1295.78 cw(c2393.7,1301.09) 2388.4,1306.39 2396.43,1314.42 ccw(c2391.13,1319.72) 2396.43,1325.03 2385,1336.46 2325,1336.46 2305,1356.46 2305,1389.09 v1(2292.95,1401.14)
